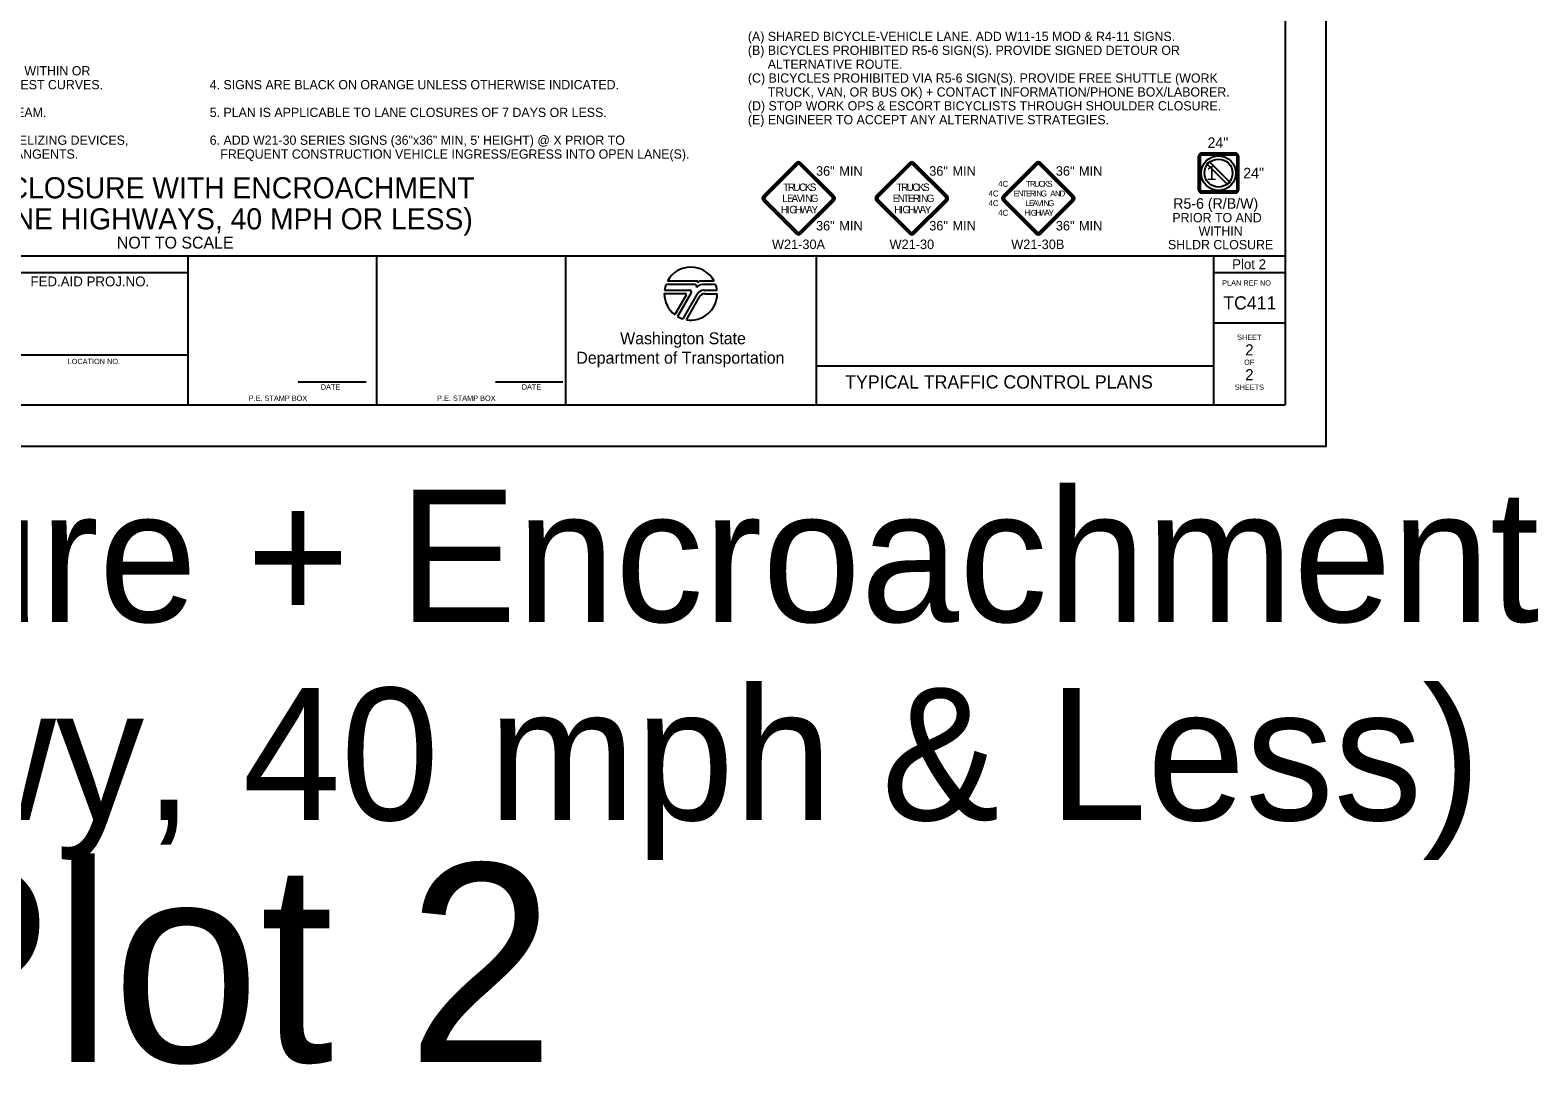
# Model space of a CAD drawing. Extents: x 99999.1 to 100055.7, y 99995 to 100010.7.
# Drawn here: x 100026.26 to 100037.66, y 99995.01 to 100002.83 of the extents above; entities that cross this region are included whole.
import ezdxf

# ---------------------------------------------------------------- set-up
doc = ezdxf.new("R2010")
doc.units = 0
for name, color, linetype in [('SH_DE_DetailHeading1Text', 7, 'Continuous'), ('SH_GI_GeneralNotesBodyText', 7, 'Continuous'), ('SH_GI_PlotLimits', 7, 'Continuous'), ('SH_GI_SheetBorder', 7, 'Continuous'), ('SH_GI_SheetLocationText', 7, 'Continuous'), ('SH_GI_SheetTextInCells', 7, 'Continuous'), ('SH_GI_TitleBlockText', 7, 'Continuous'), ('SH_GI_WSDOTLogo', 7, 'Continuous'), ('TR_SN_ConstructionSigns', 7, 'Continuous')]:
    doc.layers.add(name, color=color, linetype=linetype)

msp = doc.modelspace()

# ---------------------------------------------------------------- linework, layer by layer
at = {"layer": 'SH_GI_PlotLimits'}
msp.add_lwpolyline([(100019.062, 99999.687), (100036.062, 99999.687), (100036.062, 100010.687), (100019.062, 100010.687)], close=True, dxfattribs=at)
at = {"layer": 'SH_GI_SheetBorder'}
for p, q in [((100035.75, 100010.375), (100035.75, 100000)), ((100020, 100001.126), (100035.75, 100001.126)), ((100027.457, 100000), (100027.457, 100001.126)), ((100028.883, 100000), (100028.883, 100001.126)), ((100030.309, 100001.126), (100030.309, 100000)), ((100032.205, 100001.126), (100032.205, 100000)), ((100035.208, 100001.126), (100035.208, 100000)), ((100020, 100001.001), (100027.457, 100001.001)), ((100035.208, 100001.001), (100035.75, 100001.001)), ((100035.208, 100000.618), (100035.75, 100000.618)), ((100027.457, 100000.375), (100025.447, 100000.375)), ((100032.205, 100000.295), (100035.208, 100000.295)), ((100028.29, 100000.173), (100028.802, 100000.173)), ((100029.78, 100000.173), (100030.291, 100000.173)), ((100020, 100000), (100035.75, 100000))]:
    msp.add_line(p, q, dxfattribs=at)
at = {"layer": 'SH_GI_WSDOTLogo'}
for p, q in [((100031.289, 100000.909), (100031.07, 100000.909)), ((100031.303, 100000.935), (100031.081, 100000.935)), ((100031.433, 100000.935), (100031.335, 100000.935)), ((100031.445, 100000.909), (100031.343, 100000.909)), ((100031.343, 100000.909), (100031.343, 100000.909)), ((100031.057, 100000.84), (100031.215, 100000.84)), ((100031.059, 100000.866), (100031.25, 100000.866)), ((100031.222, 100000.828), (100031.136, 100000.681)), ((100031.261, 100000.846), (100031.157, 100000.667)), ((100031.199, 100000.649), (100031.309, 100000.839)), ((100031.224, 100000.643), (100031.324, 100000.816)), ((100031.356, 100000.866), (100031.456, 100000.866)), ((100031.365, 100000.839), (100031.457, 100000.839))]:
    msp.add_line(p, q, dxfattribs=at)
for centre, radius, start, end in [((100031.257, 100000.84), 0.2, 28.4787, 151.532), ((100031.257, 100000.84), 0.2, 159.696, 172.5057), ((100031.289, 100000.895), 0.0148, 327.8418, 89.9985), ((100031.343, 100000.861), 0.0484, 89.9953, 147.8238), ((100031.303, 100000.926), 0.00903, 329.8742, 90.0033), ((100031.335, 100000.907), 0.0287, 90.0072, 148.1676), ((100031.257, 100000.84), 0.2, 7.4943, 20.2941), ((100031.257, 100000.84), 0.2, 179.9986, 232.8433), ((100031.215, 100000.832), 0.0082, 329.7436, 90), ((100031.257, 100000.84), 0.2, 260.5455, 359.8086), ((100031.25, 100000.853), 0.0131, 329.7683, 90), ((100031.356, 100000.812), 0.0542, 90, 149.9974), ((100031.365, 100000.792), 0.0476, 90, 150.0543), ((100031.257, 100000.84), 0.2, 239.7929, 253.0448)]:
    msp.add_arc(centre, radius, start, end, dxfattribs=at)
at = {"layer": 'TR_SN_ConstructionSigns'}
for p, q in [((100032.054, 100001.829), (100031.804, 100001.579)), ((100032.059, 100001.824), (100031.809, 100001.574)), ((100031.816, 100001.567), (100032.066, 100001.817)), ((100032.078, 100001.817), (100032.329, 100001.567)), ((100032.336, 100001.574), (100032.085, 100001.824)), ((100032.341, 100001.579), (100032.09, 100001.829)), ((100032.91, 100001.829), (100032.66, 100001.579)), ((100032.915, 100001.824), (100032.665, 100001.574)), ((100032.672, 100001.567), (100032.922, 100001.817)), ((100032.934, 100001.817), (100033.185, 100001.567)), ((100033.192, 100001.574), (100032.941, 100001.824)), ((100033.197, 100001.579), (100032.946, 100001.829)), ((100033.867, 100001.829), (100033.616, 100001.579)), ((100033.872, 100001.824), (100033.621, 100001.574)), ((100033.628, 100001.567), (100033.879, 100001.817)), ((100033.891, 100001.817), (100034.141, 100001.567)), ((100034.148, 100001.574), (100033.898, 100001.824)), ((100034.153, 100001.579), (100033.903, 100001.829)), ((100035.097, 100001.883), (100035.097, 100001.621)), ((100035.097, 100001.621), (100035.097, 100001.883)), ((100035.097, 100001.883), (100035.097, 100001.621)), ((100035.102, 100001.883), (100035.102, 100001.621)), ((100035.11, 100001.621), (100035.11, 100001.883)), ((100035.378, 100001.902), (100035.116, 100001.902)), ((100035.116, 100001.902), (100035.378, 100001.902)), ((100035.378, 100001.902), (100035.116, 100001.902)), ((100035.378, 100001.897), (100035.116, 100001.897)), ((100035.116, 100001.889), (100035.378, 100001.889)), ((100035.385, 100001.883), (100035.385, 100001.621)), ((100035.392, 100001.621), (100035.392, 100001.883)), ((100035.397, 100001.621), (100035.397, 100001.883)), ((100035.397, 100001.883), (100035.397, 100001.621)), ((100035.397, 100001.621), (100035.397, 100001.883)), ((100035.378, 100001.614), (100035.116, 100001.614)), ((100035.116, 100001.607), (100035.378, 100001.607)), ((100035.116, 100001.602), (100035.378, 100001.602)), ((100035.378, 100001.602), (100035.116, 100001.602)), ((100035.116, 100001.602), (100035.378, 100001.602)), ((100031.804, 100001.543), (100032.054, 100001.292)), ((100031.809, 100001.548), (100032.059, 100001.297)), ((100032.066, 100001.304), (100031.816, 100001.555)), ((100032.329, 100001.555), (100032.078, 100001.304)), ((100032.085, 100001.297), (100032.336, 100001.548)), ((100032.09, 100001.292), (100032.341, 100001.543)), ((100032.66, 100001.543), (100032.91, 100001.292)), ((100032.665, 100001.548), (100032.915, 100001.297)), ((100032.922, 100001.304), (100032.672, 100001.555)), ((100033.185, 100001.555), (100032.934, 100001.304)), ((100032.941, 100001.297), (100033.192, 100001.548)), ((100032.946, 100001.292), (100033.197, 100001.543)), ((100033.616, 100001.543), (100033.867, 100001.292)), ((100033.621, 100001.548), (100033.872, 100001.297)), ((100033.879, 100001.304), (100033.628, 100001.555)), ((100034.141, 100001.555), (100033.891, 100001.304)), ((100033.898, 100001.297), (100034.148, 100001.548)), ((100033.903, 100001.292), (100034.153, 100001.543))]:
    msp.add_line(p, q, dxfattribs=at)
msp.add_lwpolyline([(100035.331, 100001.686), (100035.181, 100001.835), (100035.178, 100001.839), (100035.16, 100001.821), (100035.313, 100001.668), (100035.316, 100001.665), (100035.334, 100001.683), (100035.331, 100001.686)], dxfattribs=at)
for radius in [0.131, 0.106]:
    msp.add_circle((100035.247, 100001.752), radius, dxfattribs=at)
for centre, radius, start, end in [((100032.072, 100001.811), 0.0253, 45, 135), ((100032.072, 100001.811), 0.0183, 45, 135), ((100032.072, 100001.811), 0.00844, 45, 135), ((100032.928, 100001.811), 0.0253, 45, 135), ((100032.928, 100001.811), 0.0183, 45, 135), ((100032.928, 100001.811), 0.00844, 45, 135), ((100033.885, 100001.811), 0.0253, 45, 135), ((100033.885, 100001.811), 0.0183, 45, 135), ((100033.885, 100001.811), 0.00844, 45, 135), ((100035.116, 100001.883), 0.0187, 90, 180), ((100035.116, 100001.883), 0.0187, 90, 180), ((100035.116, 100001.883), 0.0187, 90, 180), ((100035.116, 100001.883), 0.0141, 90, 180), ((100035.116, 100001.883), 0.00625, 90, 180), ((100035.378, 100001.883), 0.0187, 0, 90), ((100035.378, 100001.883), 0.0187, 0, 90), ((100035.378, 100001.883), 0.0187, 0, 90), ((100035.378, 100001.883), 0.0141, 0, 90), ((100035.378, 100001.883), 0.00625, 0, 90), ((100035.116, 100001.621), 0.0187, 180, 270), ((100035.116, 100001.621), 0.0187, 180, 270), ((100035.116, 100001.621), 0.0187, 180, 270), ((100035.116, 100001.621), 0.0141, 180, 270), ((100035.116, 100001.621), 0.00625, 180, 270), ((100035.378, 100001.621), 0.0141, 270, 0), ((100035.378, 100001.621), 0.00625, 270, 0), ((100035.378, 100001.621), 0.0187, 270, 0), ((100035.378, 100001.621), 0.0187, 270, 0), ((100035.378, 100001.621), 0.0187, 270, 0), ((100031.822, 100001.561), 0.0253, 135, 225), ((100031.822, 100001.561), 0.0183, 135, 225), ((100031.822, 100001.561), 0.00844, 135, 225), ((100032.323, 100001.561), 0.00844, 315, 45), ((100032.323, 100001.561), 0.0183, 315, 45), ((100032.323, 100001.561), 0.0253, 315, 45), ((100032.678, 100001.561), 0.0253, 135, 225), ((100032.678, 100001.561), 0.0183, 135, 225), ((100032.678, 100001.561), 0.00844, 135, 225), ((100033.179, 100001.561), 0.00844, 315, 45), ((100033.179, 100001.561), 0.0183, 315, 45), ((100033.179, 100001.561), 0.0253, 315, 45), ((100033.634, 100001.561), 0.0253, 135, 225), ((100033.634, 100001.561), 0.0183, 135, 225), ((100033.634, 100001.561), 0.00844, 135, 225), ((100034.135, 100001.561), 0.00844, 315, 45), ((100034.135, 100001.561), 0.0183, 315, 45), ((100034.135, 100001.561), 0.0253, 315, 45), ((100032.072, 100001.31), 0.0253, 225, 315), ((100032.072, 100001.31), 0.0183, 225, 315), ((100032.072, 100001.31), 0.00844, 225, 315), ((100032.928, 100001.31), 0.0253, 225, 315), ((100032.928, 100001.31), 0.0183, 225, 315), ((100032.928, 100001.31), 0.00844, 225, 315), ((100033.885, 100001.31), 0.0253, 225, 315), ((100033.885, 100001.31), 0.0183, 225, 315), ((100033.885, 100001.31), 0.00844, 225, 315)]:
    msp.add_arc(centre, radius, start, end, dxfattribs=at)

# ---------------------------------------------------------------- texts
at = {"layer": 'SH_DE_DetailHeading1Text'}
for s, height, p in [('SHOULDER CLOSURE WITH ENCROACHMENT', 0.16, (100024.844, 100001.561)), ('(DIVIDED 4-LANE HIGHWAYS, 40 MPH OR LESS)', 0.16, (100024.687, 100001.326)), ('NOT TO SCALE', 0.09, (100026.918, 100001.181))]:
    msp.add_text(s, height=height, rotation=360, dxfattribs=at).set_placement(p)
at = {"layer": 'SH_GI_GeneralNotesBodyText'}
for s, p in [('(A) SHARED BICYCLE-VEHICLE LANE. ADD W11-15 MOD & R4-11 SIGNS.', (100031.689, 100002.751)), ('(B) BICYCLES PROHIBITED R5-6 SIGN(S). PROVIDE SIGNED DETOUR OR ', (100031.689, 100002.646)), ('ALTERNATIVE ROUTE.', (100031.839, 100002.541)), ('1. IF FEASIBLE, AVOID PLACING SHOULDER CLOSURE TAPER WITHIN OR ', (100023.389, 100002.491)), ('(C) BICYCLES PROHIBITED VIA R5-6 SIGN(S). PROVIDE FREE SHUTTLE (WORK ', (100031.689, 100002.436)), ('IMMEDIATELY FOLLOWING HORIZONTAL AND VERTICAL CREST CURVES.', (100023.469, 100002.386)), ('4. SIGNS ARE BLACK ON ORANGE UNLESS OTHERWISE INDICATED.', (100027.62, 100002.386)), ('TRUCK, VAN, OR BUS OK) + CONTACT INFORMATION/PHONE BOX/LABORER. ', (100031.839, 100002.331)), ('(D) STOP WORK OPS & ESCORT BICYCLISTS THROUGH SHOULDER CLOSURE.', (100031.689, 100002.226)), ('2. DISTANCE INCREASES AS WORK AREA MOVES DOWNSTREAM.', (100023.389, 100002.176)), ('5. PLAN IS APPLICABLE TO LANE CLOSURES OF 7 DAYS OR LESS.', (100027.62, 100002.176)), ('(E) ENGINEER TO ACCEPT ANY ALTERNATIVE STRATEGIES.', (100031.689, 100002.121)), ('3. 28" TRAFFIC CONES, 36" TRAFFIC CONES, 42" TALL CHANNELIZING DEVICES, ', (100023.389, 100001.966)), ('6. ADD W21-30 SERIES SIGNS (36"x36" MIN, 5\' HEIGHT) @ X PRIOR TO ', (100027.62, 100001.966)), ('OR TRAFFIC SAFETY DRUMS ALLOWED ON TAPERS AND TANGENTS.', (100023.469, 100001.861)), ('FREQUENT CONSTRUCTION VEHICLE INGRESS/EGRESS INTO OPEN LANE(S).', (100027.7, 100001.861))]:
    msp.add_text(s, height=0.07, rotation=360, dxfattribs=at).set_placement(p)
at = {"layer": 'SH_GI_SheetBorder'}
msp.add_text('PLAN REF NO', height=0.04003, dxfattribs=at).set_placement((100035.275, 100000.901))
at = {"layer": 'SH_GI_SheetLocationText'}
for s, height, p in [('Plot 2', 0.075, (100035.35, 100001.025)), ('Shldr Closure + Encroachment', 1, (100019.424, 99998.357)), ('(Divided Hwy, 40 mph & Less)', 1, (100019.248, 99996.857)), ('Plot 2', 1.5, (100025.1, 99995.027))]:
    msp.add_text(s, height=height, dxfattribs=at).set_placement(p)
at = {"layer": 'SH_GI_SheetTextInCells'}
for s, height, p in [('FED.AID PROJ.NO.', 0.07506, (100026.265, 100000.895)), ('Washington State', 0.09007, (100030.723, 100000.457)), ('SHEET', 0.04, (100035.388, 100000.49)), ('LOCATION NO.', 0.04003, (100026.546, 100000.307)), ('Department of Transportation', 0.09007, (100030.392, 100000.31)), ('OF', 0.04, (100035.441, 100000.301)), ('DATE', 0.04, (100028.46, 100000.114)), ('DATE', 0.04, (100029.979, 100000.114)), ('SHEETS', 0.04, (100035.37, 100000.112)), ('P.E. STAMP BOX', 0.04003, (100027.915, 100000.029)), ('P.E. STAMP BOX', 0.04003, (100029.339, 100000.029))]:
    msp.add_text(s, height=height, dxfattribs=at).set_placement(p)
at = {"layer": 'SH_GI_TitleBlockText'}
for s, height, p in [('TC411', 0.1, (100035.283, 100000.72)), ('2', 0.085, (100035.449, 100000.372)), ('TYPICAL TRAFFIC CONTROL PLANS', 0.1, (100032.425, 100000.122)), ('2', 0.085, (100035.449, 100000.184))]:
    msp.add_text(s, height=height, dxfattribs=at).set_placement(p)
at = {"layer": 'TR_SN_ConstructionSigns'}
for s, height, p in [('24"', 0.08, (100035.164, 100001.942)), ('36"', 0.072, (100032.204, 100001.732)), ('MIN', 0.072, (100032.38, 100001.732)), ('36"', 0.072, (100033.06, 100001.732)), ('MIN', 0.072, (100033.236, 100001.732)), ('36"', 0.072, (100034.017, 100001.732)), ('MIN', 0.072, (100034.192, 100001.732)), ('24"', 0.08, (100035.434, 100001.712)), ('R5-6 (R/B/W)', 0.08, (100034.905, 100001.482)), ('36"', 0.072, (100032.204, 100001.318)), ('MIN', 0.072, (100032.38, 100001.318)), ('36"', 0.072, (100033.06, 100001.318)), ('MIN', 0.072, (100033.236, 100001.318)), ('36"', 0.072, (100034.017, 100001.318)), ('MIN', 0.072, (100034.192, 100001.318)), ('PRIOR TO AND', 0.07, (100034.898, 100001.38)), ('W21-30A', 0.072, (100031.871, 100001.177)), ('W21-30', 0.072, (100032.76, 100001.177)), ('W21-30B', 0.072, (100033.68, 100001.177)), ('SHLDR CLOSURE', 0.07, (100034.865, 100001.176)), ('WITHIN', 0.07, (100035.097, 100001.278))]:
    msp.add_text(s, height=height, rotation=360, dxfattribs=at).set_placement(p)
for s, height, p in [('4C', 0.045, (100033.581, 100001.648)), ('T', 0.045, (100033.791, 100001.648)), ('R', 0.045, (100033.821, 100001.648)), ('U', 0.045, (100033.854, 100001.648)), ('C', 0.045, (100033.888, 100001.648)), ('K', 0.045, (100033.922, 100001.648)), ('S', 0.045, (100033.953, 100001.648)), ('1', 0.106, (100035.154, 100001.699)), ('L', 0.0562, (100031.949, 100001.533)), ('T', 0.0562, (100031.956, 100001.617)), ('E', 0.0562, (100031.985, 100001.533)), ('R', 0.0562, (100031.992, 100001.617)), ('A', 0.0562, (100032.019, 100001.533)), ('U', 0.0562, (100032.033, 100001.617)), ('V', 0.0562, (100032.059, 100001.533)), ('C', 0.0562, (100032.076, 100001.617)), ('I', 0.0562, (100032.101, 100001.533)), ('K', 0.0562, (100032.119, 100001.617)), ('N', 0.0562, (100032.122, 100001.533)), ('S', 0.0562, (100032.157, 100001.617)), ('G', 0.0562, (100032.164, 100001.533)), ('E', 0.0562, (100032.784, 100001.533)), ('T', 0.0562, (100032.812, 100001.617)), ('N', 0.0562, (100032.822, 100001.533)), ('R', 0.0562, (100032.848, 100001.617)), ('T', 0.0562, (100032.862, 100001.533)), ('U', 0.0562, (100032.889, 100001.617)), ('E', 0.0562, (100032.898, 100001.533)), ('C', 0.0562, (100032.932, 100001.617)), ('R', 0.0562, (100032.937, 100001.533)), ('K', 0.0562, (100032.975, 100001.617)), ('I', 0.0562, (100032.978, 100001.533)), ('N', 0.0562, (100032.998, 100001.533)), ('S', 0.0562, (100033.013, 100001.617)), ('G', 0.0562, (100033.041, 100001.533)), ('4C', 0.045, (100033.508, 100001.575)), ('E', 0.045, (100033.699, 100001.575)), ('N', 0.045, (100033.73, 100001.575)), ('T', 0.045, (100033.761, 100001.575)), ('E', 0.045, (100033.791, 100001.575)), ('R', 0.045, (100033.821, 100001.575)), ('I', 0.045, (100033.854, 100001.575)), ('N', 0.045, (100033.87, 100001.575)), ('G', 0.045, (100033.904, 100001.575)), ('A', 0.045, (100033.975, 100001.575)), ('N', 0.045, (100034.01, 100001.575)), ('D', 0.045, (100034.045, 100001.575)), ('H', 0.0562, (100031.939, 100001.448)), ('I', 0.0562, (100031.983, 100001.448)), ('G', 0.0562, (100032.002, 100001.448)), ('H', 0.0562, (100032.045, 100001.448)), ('W', 0.0562, (100032.084, 100001.448)), ('A', 0.0562, (100032.13, 100001.448)), ('Y', 0.0562, (100032.17, 100001.448)), ('H', 0.0562, (100032.795, 100001.448)), ('I', 0.0562, (100032.839, 100001.448)), ('G', 0.0562, (100032.858, 100001.448)), ('H', 0.0562, (100032.901, 100001.448)), ('W', 0.0562, (100032.94, 100001.448)), ('A', 0.0562, (100032.986, 100001.448)), ('Y', 0.0562, (100033.026, 100001.448)), ('4C', 0.045, (100033.508, 100001.502)), ('4C', 0.045, (100033.581, 100001.429)), ('H', 0.045, (100033.778, 100001.429)), ('L', 0.045, (100033.786, 100001.502)), ('I', 0.045, (100033.813, 100001.429)), ('E', 0.045, (100033.815, 100001.502)), ('G', 0.045, (100033.828, 100001.429)), ('A', 0.045, (100033.842, 100001.502)), ('H', 0.045, (100033.863, 100001.429)), ('V', 0.045, (100033.874, 100001.502)), ('W', 0.045, (100033.894, 100001.429)), ('I', 0.045, (100033.908, 100001.502)), ('N', 0.045, (100033.924, 100001.502)), ('A', 0.045, (100033.931, 100001.429)), ('G', 0.045, (100033.958, 100001.502)), ('Y', 0.045, (100033.962, 100001.429))]:
    msp.add_text(s, height=height, dxfattribs=at).set_placement(p)

doc.saveas('drawing.dxf')
